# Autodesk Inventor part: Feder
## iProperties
Created: 2009-12
Part Number: Feder
Document SubType Name: Modeling
Designer: bulent
Density: 1 g/cm^3
Author: bulent
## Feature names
1. Extrusion1
2. Extrusion2
